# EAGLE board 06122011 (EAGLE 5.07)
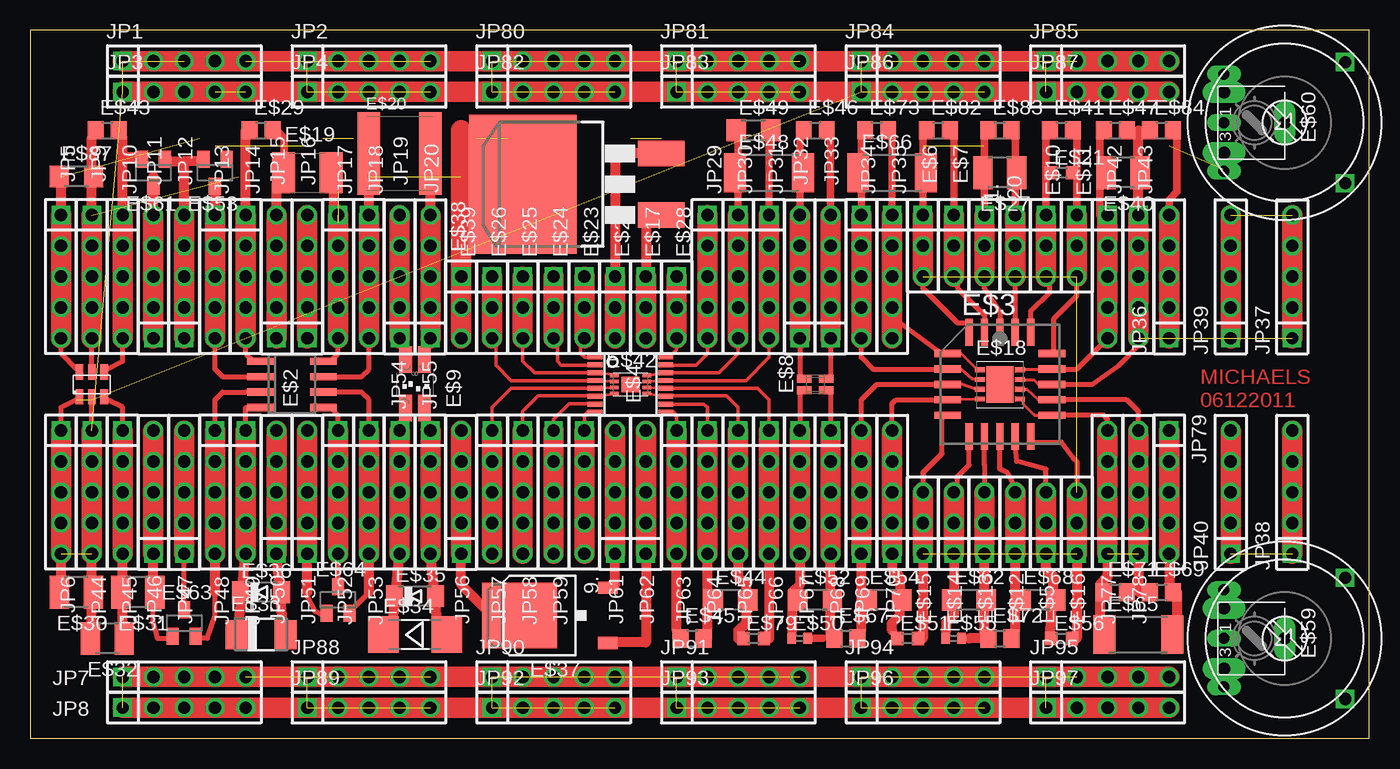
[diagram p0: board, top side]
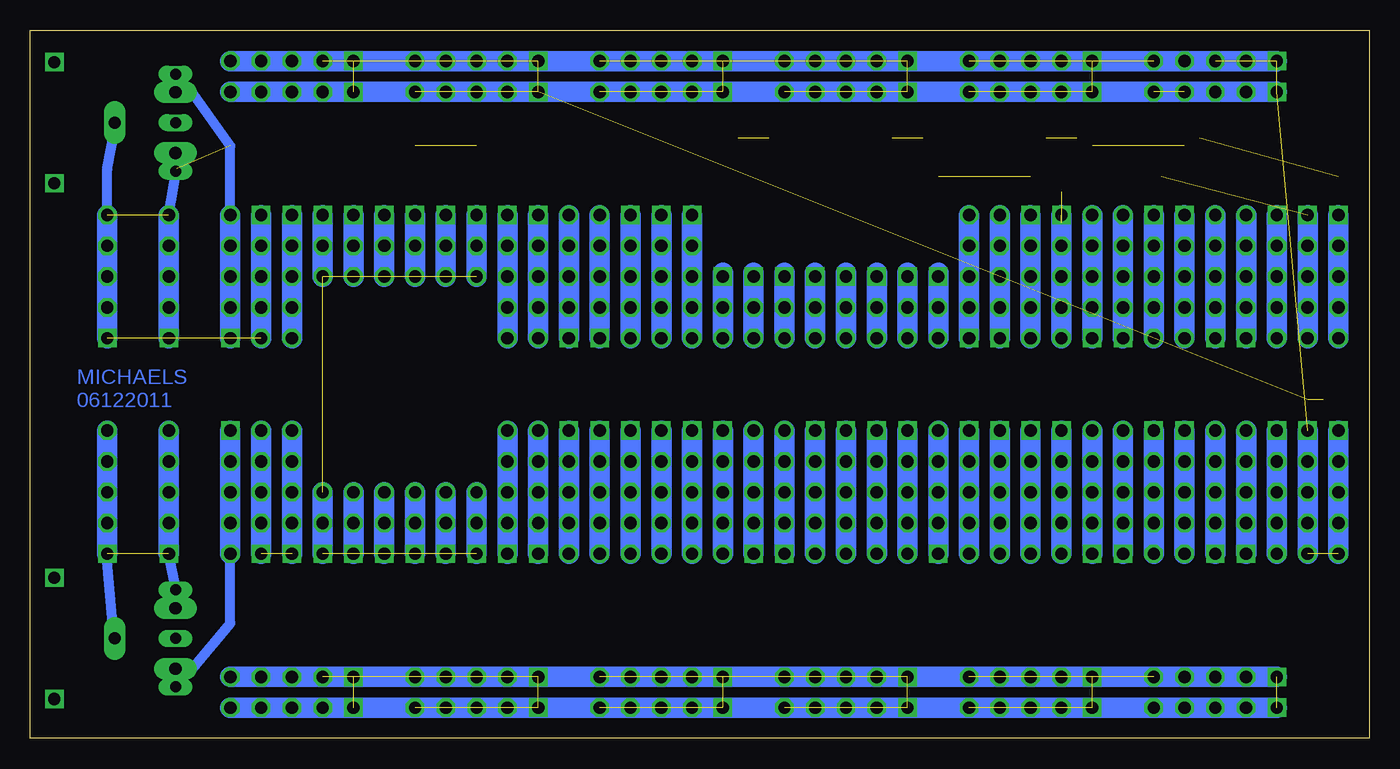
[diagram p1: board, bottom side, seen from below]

Size 110.49 x 58.42 mm. Coordinates in mm from the lower left corner, seen from the top.
Outline: 0,0 110.49,0 110.49,58.42 0,58.42 0,0
Copper layers (1*16): Top 0.035mm / dielectric 1.5mm / Bottom 0.035mm
Design rules "default": minimum track width 10mil, minimum drill 24mil, track to track 8mil, track to pad 8mil, pad to pad 8mil, via to via 8mil, smd to smd 8mil, copper to edge 40mil, drill to drill 8mil, minimum pad ring 10mil, minimum via ring 8mil, stop-mask expansion 4mil, vias tented up to drill 0mil, thermal gap 10mil

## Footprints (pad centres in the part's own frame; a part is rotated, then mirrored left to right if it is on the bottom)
1X03 = drill 1.016 square: 1 -2.54,0 | drill 1.016 octagon: 2 0,0; 3 2.54,0
1X05 = drill 1.016 square: 1 -5.08,0 | drill 1.016 octagon: 2 -2.54,0; 3 0,0; 4 2.54,0; 5 5.08,0
SOT23-6 = smd 0.635 x 1.27: 1 -1.016,-1.016; 2 0,-1.016; 3 1.016,-1.016; 4 1.016,1.016; 5 0,1.016; 6 -1.016,1.016
SO08 = smd 0.6 x 2.2: 1 -1.905,-2.6; 2 -0.635,-2.6; 3 0.635,-2.6; 4 1.905,-2.6; 5 1.905,2.6; 6 0.635,2.6; 7 -0.635,2.6; 8 -1.905,2.6
PLCC20S = smd 0.6 x 2.2: 1 0,4.3; 2 -1.27,4.3; 3 -2.54,4.3; 9 -2.54,-4.3; 10 -1.27,-4.3; 11 0,-4.3; 12 1.27,-4.3; 13 2.54,-4.3; 19 2.54,4.3; 20 1.27,4.3 | smd 2.2 x 0.6: 4 -4.3,2.54; 5 -4.3,1.27; 6 -4.3,0; 7 -4.3,-1.27; 8 -4.3,-2.54; 14 4.3,-2.54; 15 4.3,-1.27; 16 4.3,0; 17 4.3,1.27; 18 4.3,2.54
SSOP16 = smd 0.4 x 1.2: 1 -2.275,-2.925; 2 -1.625,-2.925; 3 -0.975,-2.925; 4 -0.325,-2.925; 5 0.325,-2.925; 6 0.975,-2.925; 7 1.625,-2.925; 8 2.275,-2.925; 9 2.275,2.925; 10 1.625,2.925; 11 0.975,2.925; 12 0.325,2.925; 13 -0.325,2.925; 14 -0.975,2.925; 15 -1.625,2.925; 16 -2.275,2.925
GM1WA55311A = smd 0.65 x 1.2: 1 -0.475,0.9; 2 -0.475,-0.9; 3 0.475,-0.9; 4 0.475,0.9
DUOLEDSMD = smd 1.067 x 2.184: AGRN 0.77,1.95; ARED -0.77,1.95; CGRN 0.77,-2.05; CRED -0.77,-2.05
DFN8-4X4 = smd 0.8 x 0.4: 1 -1.65,1.2; 2 -1.65,0.4; 3 -1.65,-0.4; 4 -1.65,-1.2; 5 1.65,-1.2; 6 1.65,-0.4; 7 1.65,0.4; 8 1.65,1.2 | smd 2.2 x 3: EXP 0,0
C1812 = smd 1.9 x 3.4: 1 -1.95,0; 2 1.95,0
C2225K = smd 1.85 x 6.8: 1 -2.55,0; 2 2.55,0
R0603 = smd 1 x 1.1: 1 -0.85,0; 2 0.85,0
R1210 = smd 1.6 x 2.7: 1 -1.4,0; 2 1.4,0
R0805 = smd 1.3 x 1.5: 1 -0.95,0; 2 0.95,0
DO-214AC = smd 1.8 x 2.4: A 2.025,0; C -2.025,0
MELF-MLL41 = smd 2.5 x 3: A 2.625,0; C -2.625,0
MINIMELF = smd 1.4 x 1.8: A 1.7,0; C -1.7,0
D-PAK_TO252AA = smd 1 x 1.6: 1 -2.28,-4.8; 3 2.28,-4.8 | smd 5.4 x 6.2: 4 0,2.5
D2PACK = smd 2.083 x 3.81: 1 -2.54,-8.89; 3 2.54,-8.89 | smd 11.43 x 8.89: 2 0,2.54
DFN-2X3 = smd 0.7 x 0.3: 1 -1.325,0.75; 2 -1.325,0.25; 3 -1.325,-0.25; 4 -1.325,-0.75; 5 1.325,-0.75; 6 1.325,-0.25; 7 1.325,0.25; 8 1.325,0.75 | smd 1.5 x 1.3: EXP 0,0
R1206 = smd 1.6 x 1.803: 1 -1.422,0; 2 1.422,0
R2512 = smd 1.8 x 3.2: 1 -2.8,0; 2 2.8,0
R0402 = smd 0.7 x 0.9: 1 -0.65,0; 2 0.65,0
SOT23 = smd 1 x 1.4: 1 -0.95,-1.1; 2 0.95,-1.1; 3 0,1.1
RANDL = drill 0.9 long: A -4,5; E 4,5; S 0,5 | drill 1 square: P$1 -5,-5; P$2 5,-5
EVND8AA = drill 1 pad 1.778 long: A -2.5,-2.5; E 2.5,-2.5; S 0,2.5

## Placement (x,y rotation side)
1.  [1X03]  78.74,40.64 270 top
9.  [1X05]  45.72,20.32 270 top
20  [1X03]  81.28,40.64 270 top
E$1  [SOT23-6]  5.08,29.21 0 top
E$2  [SO08]  21.59,29.21 270 top
E$3  [PLCC20S]  80.01,29.21 0 top
E$4  [SSOP16]  49.53,29.21 270 top
E$5  [1X03]  83.82,17.78 90 top
E$6  [1X03]  73.66,40.64 270 top
E$7  [1X03]  76.2,40.64 270 top
E$8  [GM1WA55311A]  64.77,29.21 90 top
E$9  [DUOLEDSMD]  31.75,29.21 180 top
E$10  [1X03]  83.82,40.64 270 top
E$11  [1X03]  86.36,40.64 270 top
E$12  [1X03]  81.28,17.78 90 top
E$13  [1X03]  78.74,17.78 90 top
E$14  [1X03]  76.2,17.78 90 top
E$15  [1X03]  73.66,17.78 90 top
E$16  [1X03]  86.36,17.78 90 top
E$17  [1X03]  50.8,35.56 270 top
E$18  [DFN8-4X4]  80.01,29.21 0 top
E$19  [C1812]  22.86,46.67 0 top
E$20  [C2225K]  30.48,48.26 0 top
E$21  [R0603]  85.09,46.67 0 top
E$22  [1X03]  48.26,35.56 270 top
E$23  [1X03]  45.72,35.56 270 top
E$24  [1X03]  43.18,35.56 270 top
E$25  [1X03]  40.64,35.56 270 top
E$26  [1X03]  38.1,35.56 270 top
E$27  [R1210]  80.01,46.67 180 top
E$28  [1X03]  53.34,35.56 270 top
E$29  [R0805]  19.05,50.16 0 top
E$30  [R1210]  3.81,12.06 180 top
E$31  [R1210]  8.89,12.06 180 top
E$32  [R1210]  6.35,8.26 180 top
E$33  [DO-214AC]  19.05,8.57 0 top
E$34  [MELF-MLL41]  31.75,8.57 0 top
E$35  [MINIMELF]  31.75,11.75 0 top
E$36  [MINIMELF]  19.05,12.06 0 top
E$37  [D-PAK_TO252AA]  42.86,10.16 90 top
E$38  [D2PACK]  43.18,45.72 90 top
E$39  [1X03]  35.56,35.56 270 top
E$40  [R1210]  90.17,46.67 180 top
E$41  [R0805]  85.09,50.16 0 top
E$42  [DFN-2X3]  49.53,29.21 0 top
E$43  [R0805]  6.35,50.16 0 top
E$44  [R1206]  57.78,11.43 0 top
E$45  [R0805]  54.61,8.26 0 top
E$46  [R0805]  64.77,50.16 0 top
E$47  [R0805]  89.53,50.16 0 top
E$48  [R2512]  60.96,46.67 0 top
E$49  [R1206]  59.69,50.16 0 top
E$50  [R0402]  63.5,8.26 0 top
E$51  [R0603]  72.39,8.26 0 top
E$52  [R1206]  64.77,11.43 0 top
E$53  [SOT23]  15.24,46.67 180 top
E$54  [R1206]  70.48,11.43 0 top
E$55  [R0402]  76.2,8.26 0 top
E$56  [R0603]  85.09,8.26 0 top
E$57  [RANDL]  103.5,50.8 90 top
E$58  [RANDL]  103.5,8.26 90 top
E$59  [EVND8AA]  101.02,8.26 270 top
E$60  [EVND8AA]  101.02,50.8 270 top
E$61  [SOT23]  10.16,46.67 180 top
E$62  [R1206]  77.47,11.43 0 top
E$63  [SOT23]  12.7,9.53 0 top
E$64  [SOT23]  25.4,11.43 0 top
E$65  [R2512]  91.44,8.57 0 top
E$66  [R2512]  71.12,46.67 0 top
E$67  [R0805]  67.31,8.26 0 top
E$68  [R1206]  83.19,11.43 0 top
E$69  [R0805]  93.34,12.06 0 top
E$71  [R0805]  89.53,12.06 0 top
E$72  [R0805]  80.01,8.26 0 top
E$73  [R0805]  69.85,50.16 0 top
E$79  [R0603]  59.69,8.26 0 top
E$82  [R0805]  74.93,50.16 0 top
E$83  [R0805]  80.01,50.16 0 top
E$84  [R0805]  93.34,50.16 0 top
E$87  [R1206]  3.81,46.35 0 top
JP1  [1X05]  12.7,55.88 0 top
JP2  [1X05]  27.94,55.88 0 top
JP3  [1X05]  12.7,53.34 0 top
JP4  [1X05]  27.94,53.34 0 top
JP5  [1X05]  2.54,38.1 270 top
JP6  [1X05]  2.54,20.32 270 top
JP7  [1X05]  12.7,5.08 0 top
JP8  [1X05]  12.7,2.54 0 top
JP9  [1X05]  5.08,38.1 270 top
JP10  [1X05]  7.62,38.1 270 top
JP11  [1X05]  10.16,38.1 90 top
JP12  [1X05]  12.7,38.1 90 top
JP13  [1X05]  15.24,38.1 270 top
JP14  [1X05]  17.78,38.1 270 top
JP15  [1X05]  20.32,38.1 90 top
JP16  [1X05]  22.86,38.1 90 top
JP17  [1X05]  25.4,38.1 270 top
JP18  [1X05]  27.94,38.1 270 top
JP19  [1X05]  30.48,38.1 90 top
JP20  [1X05]  33.02,38.1 90 top
JP29  [1X05]  55.88,38.1 270 top
JP30  [1X05]  58.42,38.1 270 top
JP31  [1X05]  60.96,38.1 270 top
JP32  [1X05]  63.5,38.1 90 top
JP33  [1X05]  66.04,38.1 90 top
JP34  [1X05]  68.58,38.1 270 top
JP35  [1X05]  71.12,38.1 270 top
JP36  [1X05]  93.98,38.1 90 top
JP37  [1X05]  104.14,38.1 90 top
JP38  [1X05]  104.14,20.32 90 top
JP39  [1X05]  99.06,38.1 90 top
JP40  [1X05]  99.06,20.32 90 top
JP42  [1X05]  88.9,38.1 270 top
JP43  [1X05]  91.44,38.1 270 top
JP44  [1X05]  5.08,20.32 270 top
JP45  [1X05]  7.62,20.32 270 top
JP46  [1X05]  10.16,20.32 90 top
JP47  [1X05]  12.7,20.32 90 top
JP48  [1X05]  15.24,20.32 270 top
JP49  [1X05]  17.78,20.32 270 top
JP50  [1X05]  20.32,20.32 90 top
JP51  [1X05]  22.86,20.32 90 top
JP52  [1X05]  25.4,20.32 270 top
JP53  [1X05]  27.94,20.32 270 top
JP54  [1X05]  30.48,20.32 270 top
JP55  [1X05]  33.02,20.32 270 top
JP56  [1X05]  35.56,20.32 90 top
JP57  [1X05]  38.1,20.32 270 top
JP58  [1X05]  40.64,20.32 270 top
JP59  [1X05]  43.18,20.32 270 top
JP61  [1X05]  48.26,20.32 90 top
JP62  [1X05]  50.8,20.32 90 top
JP63  [1X05]  53.34,20.32 270 top
JP64  [1X05]  55.88,20.32 270 top
JP65  [1X05]  58.42,20.32 270 top
JP66  [1X05]  60.96,20.32 270 top
JP67  [1X05]  63.5,20.32 270 top
JP68  [1X05]  66.04,20.32 270 top
JP69  [1X05]  68.58,20.32 90 top
JP70  [1X05]  71.12,20.32 90 top
JP77  [1X05]  88.9,20.32 90 top
JP78  [1X05]  91.44,20.32 90 top
JP79  [1X05]  93.98,20.32 270 top
JP80  [1X05]  43.18,55.88 0 top
JP81  [1X05]  58.42,55.88 0 top
JP82  [1X05]  43.18,53.34 0 top
JP83  [1X05]  58.42,53.34 0 top
JP84  [1X05]  73.66,55.88 0 top
JP85  [1X05]  88.9,55.88 0 top
JP86  [1X05]  73.66,53.34 0 top
JP87  [1X05]  88.9,53.34 0 top
JP88  [1X05]  27.94,5.08 0 top
JP89  [1X05]  27.94,2.54 0 top
JP90  [1X05]  43.18,5.08 0 top
JP91  [1X05]  58.42,5.08 0 top
JP92  [1X05]  43.18,2.54 0 top
JP93  [1X05]  58.42,2.54 0 top
JP94  [1X05]  73.66,5.08 0 top
JP95  [1X05]  88.9,5.08 0 top
JP96  [1X05]  73.66,2.54 0 top
JP97  [1X05]  88.9,2.54 0 top

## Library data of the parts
1. 9. 20 E$5-E$7 E$10-E$17 E$22-E$26 E$28 E$39 JP1-JP20 JP29-JP40 JP42-JP59 JP61-JP70 JP77-JP97 = pinhead(2)
E$1 = microchip-5
E$2-E$4 = linear
E$8 E$9 = led
E$18 E$42 = microchip
E$19-E$21 E$27 E$29-E$32 E$40 E$41 E$43-E$52 E$54-E$56 E$62 E$65-E$69 E$71-E$73 E$79 E$82-E$84 E$87 = rcl
E$33-E$36 = diode
E$37 E$38 = transistor-power
E$53 E$61 E$63 E$64 = transistor-npn
E$57-E$60 = pot

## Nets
N$1: JP1.1 JP1.2 JP1.3
N$2: JP2.1 JP2.2
N$3: JP3.4 JP3.5
N$76: JP80.1 JP80.2 JP80.3
N$77: JP81.1 JP81.2
N$78: JP82.4 JP82.5
N$80: JP84.1 JP84.2 JP84.3
N$81: JP85.1 JP85.2
N$82: JP86.4 JP86.5
N$84: JP88.1 JP88.2
N$86: JP90.1 JP90.2 JP90.3
N$87: JP91.1 JP91.2
N$88: JP92.4 JP92.5
N$90: JP94.1 JP94.2 JP94.3
N$91: JP95.1 JP95.2
N$92: JP96.4 JP96.5
S$25: 20.3
S$30: E$7.3
S$31: E$6.3
S$42: E$5.1
S$43: E$14.3
S$45: E$17.1

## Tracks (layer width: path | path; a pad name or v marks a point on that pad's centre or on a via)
N$1  (2 unrouted)
N$2  (1 unrouted)
N$3  (1 unrouted)
N$4  (1 unrouted)
  Top 0.406: 3.81,30.48 2.54,31.75 2.54,33.02
  Top 0.813: 2.54,43.18 2.54,46.35
  Top 1.676: 2.54,33.02 2.54,43.18
N$5  (1 unrouted)
  Top 0.406: 5.08,30.48 5.08,33.02
  Top 0.813: 5.08,43.18 5.08,49.53
  Top 1.676: 5.08,33.02 5.08,43.18
N$6
  Top 0.406: 6.35,30.48 7.62,31.11 7.62,33.02
  Top 0.813: 7.62,43.18 7.62,49.53
  Top 1.676: 7.62,33.02 7.62,43.18
N$7  (3 unrouted)
  Top 0.406: 85.09,29.21 87.63,29.21 89.85,30.8 91.44,32.38 91.44,33.02
  Top 0.61: 93.98,43.18 93.98,44.45 94.61,45.09 94.61,50.16
  Top 1.676: 91.44,33.02 91.44,43.18 | 93.98,33.02 93.98,43.18 | 99.06,33.02 99.06,43.18 | 104.14,33.02 104.14,43.18
N$8
  Top 1.676: 88.9,33.02 88.9,43.18
N$10
  Top 0.813: 68.58,8.89 68.58,15.24
N$11
  Top 0.813: 66.04,12.06 66.04,15.24
N$12
  Top 0.406: 66.04,11.43 66.04,12.06
  Top 0.813: 66.04,8.26 66.04,11.43
N$14
  Top 0.813: 81.28,8.89 81.28,15.24
N$15
  Top 0.305: 71.44,37.15 71.12,37.47 71.12,38.1
  Top 0.406: 75.25,31.75 71.75,34.29 71.44,37.15
  Top 0.61: 71.12,43.18 71.12,50.16
  Top 1.676: 71.12,33.02 71.12,38.1 71.12,43.18
N$16
  Top 0.813: 78.74,12.06 78.74,15.24
N$17
  Top 0.406: 78.74,11.43 78.74,12.06
  Top 0.813: 78.74,8.26 78.74,11.43
N$18
  Top 0.406: 11.75,8.26 10.48,8.26 10.16,9.53 10.16,12.7
  Top 0.813: 10.16,12.06 10.16,12.7 10.16,15.24
N$19
  Top 0.61: 60.96,43.18 60.96,49.53
  Top 1.676: 60.96,33.02 60.96,43.18
N$20
  Top 0.305: 52.7,30.16 56.83,30.16 58.42,31.75 58.42,33.02
  Top 0.61: 58.42,43.18 58.42,49.85
  Top 1.676: 58.42,33.02 58.42,43.18
N$21
  Top 0.305: 52.7,30.8 54.93,30.8 55.88,31.75 55.88,33.02
  Top 1.676: 55.88,33.02 55.88,43.18
N$25
  Top 0.305: 46.04,31.43 45.72,31.43 45.4,31.75 45.4,32.7 45.72,33.02
N$26
  Top 0.305: 46.04,30.8 43.81,30.8 43.5,31.11 43.5,32.7 43.18,33.02
N$27
  Top 0.305: 46.04,30.16 41.59,30.16 40.64,31.11 40.64,33.02
N$28
  Top 0.305: 46.35,29.53 39.69,29.53 38.42,30.8 38.42,32.7 38.1,33.02
N$29
  Top 1.676: 35.56,33.02 35.56,50.16
N$30
  Top 0.813: 33.02,43.18 33.02,45.72
  Top 1.676: 33.02,33.02 33.02,43.18
N$31
  Top 1.676: 30.48,33.02 30.48,43.18
N$32
  Top 0.406: 24.77,29.84 27.3,29.84 27.94,30.48 27.94,33.02
  Top 0.813: 27.94,43.18 27.94,46.04
  Top 1.676: 27.94,33.02 27.94,43.18
N$33  (2 unrouted)
  Top 0.406: 24.77,31.11 25.4,31.75 25.4,33.02
  Top 1.676: 25.4,33.02 25.4,43.18
N$34
  Top 1.676: 22.86,33.02 22.86,43.18
N$35
  Top 1.676: 20.32,33.02 20.32,43.18
N$36
  Top 0.406: 18.41,31.11 17.78,31.75 17.78,33.02
  Top 1.676: 17.78,33.02 17.78,43.18
N$37
  Top 0.406: 18.41,29.84 15.88,29.84 15.24,30.48 15.24,33.02
  Top 1.676: 15.24,33.02 15.24,43.18
N$38
  Top 1.676: 12.7,33.02 12.7,43.18
N$39
  Top 0.813: 10.16,43.18 10.16,46.35
  Top 1.676: 10.16,33.02 10.16,43.18
N$40  (5 unrouted)
  Top 0.406: 3.81,27.94 2.54,27.3 2.54,25.4 | 5.08,25.4 5.08,27.94
  Top 1.676: 5.08,15.24 5.08,25.4 | 83.82,55.88 93.98,55.88 | 83.82,53.34 93.98,53.34 | 68.58,53.34 78.74,53.34 | 68.58,55.88 78.74,55.88 | 2.54,15.24 2.54,25.4
N$41
  Top 0.813: 93.98,15.24 93.98,12.7 94.61,12.06 94.61,8.26
  Top 1.676: 93.98,15.24 93.98,25.4
N$42
  Top 0.406: 85.41,27.94 90.49,27.94 91.44,26.99 91.44,25.08
  Top 0.813: 91.44,15.24 91.44,12.06
  Top 1.676: 91.44,15.24 91.44,25.08 91.44,25.4
N$43
  Top 0.406: 85.41,26.67 88.58,26.67 88.9,26.35 88.9,25.4
  Top 1.676: 88.9,15.24 88.9,25.4
N$44
  Top 0.813: 7.62,8.89 7.62,15.24
N$45
  Top 0.406: 82.55,24.45 85.09,24.45 86.04,23.18 86.36,22.86 86.36,20.64
N$46
  Top 0.813: 5.08,8.89 5.08,15.24
N$47
  Top 0.406: 80.01,23.81 80.01,22.23 80.64,21.91 81.28,20.64
N$48
  Top 0.406: 78.74,24.13 78.74,22.54 78.74,20.64
N$49
  Top 0.813: 2.54,12.06 2.54,15.24
N$50
  Top 0.305: 71.12,25.4 71.12,25.72
  Top 0.406: 74.93,27.94 71.44,27.94 71.12,27.62 71.12,25.72
  Top 1.676: 71.12,15.24 71.12,25.4
N$51
  Top 0.406: 74.93,29.21 69.85,29.21 68.58,27.94 68.58,25.4
  Top 1.676: 68.58,15.24 68.58,25.4
N$52
  Top 1.676: 66.04,15.24 66.04,25.4
N$53
  Top 0.813: 63.5,15.24 63.5,12.7 62.87,12.06 62.87,8.89
  Top 1.676: 63.5,15.24 63.5,25.4
N$54
  Top 0.813: 60.96,15.24 60.96,8.26
  Top 1.676: 60.96,15.24 60.96,25.4
N$55
  Top 0.305: 52.39,28.26 57.47,28.26 58.42,27.3 58.42,25.4
  Top 1.676: 58.42,15.24 58.42,25.4
N$56
  Top 0.305: 52.7,27.56 55.56,27.56 55.88,27.3 55.88,25.4
  Top 1.676: 55.88,15.24 55.88,25.4
N$57
  Top 0.305: 53.02,26.99 53.34,26.67 53.34,25.08
  Top 1.676: 53.34,15.24 53.34,25.08 53.34,25.4
N$58
  Top 0.813: 50.8,15.24 50.8,7.94 48.26,7.94
  Top 1.676: 50.8,15.24 50.8,25.4
N$59
  Top 0.813: 48.26,12.7 48.26,15.24
  Top 1.676: 48.26,15.24 48.26,25.4
N$60
  Top 0.305: 46.35,26.99 46.04,26.99 45.72,26.67 45.72,25.4
  Top 1.676: 45.72,15.24 45.72,25.4
N$61
  Top 0.305: 46.04,27.62 44.45,27.62 43.18,26.35 43.18,25.4
  Top 1.676: 43.18,15.24 43.18,25.4
N$62
  Top 0.305: 46.04,28.26 41.91,28.26 40.64,26.99 40.64,25.4
  Top 1.676: 40.64,15.24 40.64,25.4
N$63
  Top 0.305: 46.04,28.89 39.69,28.89 38.1,27.3 38.1,25.4
  Top 1.676: 38.1,15.24 38.1,25.4
N$64
  Top 1.676: 35.56,15.24 35.56,25.4
N$65
  Top 1.676: 33.02,15.24 33.02,25.4
N$66
  Top 1.676: 30.48,15.24 30.48,25.4
N$67
  Top 0.406: 24.77,28.57 27.3,28.57 27.94,27.94 27.94,25.4
  Top 1.676: 27.94,15.24 27.94,25.4
N$68
  Top 0.406: 24.77,27.3 25.4,26.67 25.4,25.4
  Top 1.676: 25.4,15.24 25.4,25.4
N$69
  Top 1.676: 22.86,15.24 22.86,25.4
N$70
  Top 1.676: 20.32,15.24 20.32,25.4
N$71
  Top 0.406: 17.78,25.4 17.78,27.3
  Top 1.676: 17.78,15.24 17.78,25.4
N$72
  Top 0.406: 17.78,28.57 15.88,28.57 15.24,27.94 15.24,25.4
  Top 1.676: 15.24,15.24 15.24,25.4
N$73
  Top 0.406: 12.7,10.16 12.7,15.24
  Top 1.676: 12.7,15.24 12.7,25.4
N$74
  Top 1.676: 10.16,15.24 10.16,25.4
N$75
  Top 0.406: 6.35,27.94 7.62,27.3 7.62,25.4
  Top 1.676: 7.62,15.24 7.62,25.4
N$76  (2 unrouted)
N$77  (1 unrouted)
N$78  (1 unrouted)
N$79  (3 unrouted)
  Top 1.676: 53.34,55.88 63.5,55.88 | 53.34,53.34 63.5,53.34 | 38.1,53.34 48.26,53.34 | 38.1,55.88 48.26,55.88
N$80  (2 unrouted)
N$81  (1 unrouted)
N$82  (1 unrouted)
N$83  (3 unrouted)
  Top 1.676: 22.86,55.88 33.02,55.88 | 22.86,53.34 33.02,53.34 | 7.62,53.34 17.78,53.34 | 7.62,55.88 17.78,55.88
N$84  (1 unrouted)
N$85  (3 unrouted)
  Top 1.676: 68.58,2.54 78.74,2.54 | 68.58,5.08 78.74,5.08 | 83.82,5.08 93.98,5.08 | 83.82,2.54 93.98,2.54
N$86  (2 unrouted)
N$87  (1 unrouted)
N$88  (1 unrouted)
N$89  (3 unrouted)
  Top 1.676: 53.34,5.08 63.5,5.08 | 53.34,2.54 63.5,2.54 | 38.1,2.54 48.26,2.54 | 38.1,5.08 48.26,5.08
N$90  (2 unrouted)
N$91  (1 unrouted)
N$92  (1 unrouted)
N$93  (3 unrouted)
  Top 1.676: 22.86,5.08 33.02,5.08 | 22.86,2.54 33.02,2.54 | 7.62,2.54 17.78,2.54 | 7.62,5.08 17.78,5.08
N$94
  Bottom 1.676: 2.54,33.02 2.54,43.18
N$95
  Bottom 1.676: 5.08,33.02 5.08,43.18
N$96
  Bottom 1.676: 7.62,33.02 7.62,43.18
N$97
  Bottom 1.676: 10.16,33.02 10.16,43.18
N$98
  Bottom 1.676: 12.7,33.02 12.7,43.18
N$99
  Bottom 1.676: 15.24,33.02 15.24,43.18
N$100
  Bottom 1.676: 17.78,33.02 17.78,43.18
N$101
  Bottom 1.676: 20.32,33.02 20.32,43.18
N$102
  Bottom 1.676: 22.86,33.02 22.86,43.18
N$103
  Bottom 1.676: 25.4,33.02 25.4,43.18
N$104
  Bottom 1.676: 27.94,33.02 27.94,43.18
N$105
  Bottom 1.676: 30.48,33.02 30.48,43.18
N$106
  Bottom 1.676: 33.02,33.02 33.02,43.18
N$107
  Bottom 1.676: 35.56,33.02 35.56,38.42
N$108
  Bottom 1.676: 38.1,33.02 38.1,38.42
N$109
  Bottom 1.676: 40.64,33.02 40.64,38.42
N$110
  Bottom 1.676: 43.18,33.02 43.18,38.42
N$111
  Bottom 1.676: 45.72,33.02 45.72,38.42
N$112
  Bottom 1.676: 48.26,33.02 48.26,38.42
N$113
  Bottom 1.676: 50.8,33.02 50.8,38.42
N$114
  Bottom 1.676: 53.34,33.02 53.34,38.42
N$115
  Bottom 1.676: 55.88,33.02 55.88,43.18
N$116
  Bottom 1.676: 58.42,33.02 58.42,43.18
N$117
  Bottom 1.676: 60.96,33.02 60.96,43.18
N$118
  Bottom 1.676: 63.5,33.02 63.5,43.18
N$119
  Bottom 1.676: 66.04,33.02 66.04,43.18
N$120
  Bottom 1.676: 68.58,33.02 68.58,43.18
N$121
  Bottom 1.676: 71.12,33.02 71.12,43.18
N$122
  Top 0.813: 22.86,12.06 22.86,15.24
N$123
  Top 0.813: 20.95,8.26 20.32,15.24
N$124
  Top 0.813: 17.14,8.89 17.78,15.24
N$125
  Top 0.406: 13.65,8.26 14.61,8.26 15.24,10.16 15.24,12.06
  Top 0.813: 15.24,12.06 15.24,15.24
N$126
  Top 0.813: 35.56,15.24 35.56,12.7 38.73,9.53
N$127
  Top 0.813: 33.66,8.89 33.02,15.24
N$128
  Bottom 1.676: 88.9,33.02 88.9,43.18
N$129  (3 unrouted)
  Bottom 0.813: 97.16,53.34 93.98,48.9 93.98,42.55 | 103.5,50.16 104.14,46.99 104.14,43.18 | 99.06,43.18 98.42,46.99
  Bottom 1.676: 104.14,33.02 104.14,43.18 | 93.98,43.18 93.98,42.55 93.98,33.02 | 91.44,33.02 91.44,43.18 | 99.06,33.02 99.06,43.18
N$130  (5 unrouted)
  Bottom 1.676: 5.08,15.24 5.08,25.4 | 7.62,55.88 17.78,55.88 | 7.62,53.34 17.78,53.34 | 22.86,53.34 33.02,53.34 | 22.86,55.88 33.02,55.88 | 2.54,15.24 2.54,25.4
N$131
  Bottom 1.676: 7.62,15.24 7.62,25.4
N$132
  Bottom 1.676: 10.16,15.24 10.16,25.4
N$133
  Bottom 1.676: 12.7,15.24 12.7,25.4
N$134
  Bottom 1.676: 15.24,15.24 15.24,25.4
N$135
  Bottom 1.676: 17.78,15.24 17.78,25.4
N$136
  Bottom 1.676: 20.32,15.24 20.32,25.4
N$137
  Bottom 1.676: 22.86,15.24 22.86,25.4
N$138
  Bottom 1.676: 25.4,15.24 25.4,25.4
N$139
  Bottom 1.676: 27.94,15.24 27.94,25.4
N$140
  Bottom 1.676: 30.48,15.24 30.48,25.4
N$141
  Bottom 1.676: 33.02,15.24 33.02,25.4
N$142
  Bottom 1.676: 35.56,15.24 35.56,25.4
N$143
  Bottom 1.676: 38.1,15.24 38.1,25.4
N$144
  Bottom 1.676: 40.64,15.24 40.64,25.4
N$145
  Bottom 1.676: 43.18,15.24 43.18,25.4
N$146
  Bottom 1.676: 45.72,15.24 45.72,25.4
N$147
  Bottom 1.676: 48.26,15.24 48.26,25.4
N$148
  Bottom 1.676: 50.8,15.24 50.8,25.4
N$149
  Bottom 1.676: 53.34,15.24 53.34,25.4
N$150
  Bottom 1.676: 55.88,15.24 55.88,25.4
N$151
  Bottom 1.676: 58.42,15.24 58.42,25.4
N$152
  Bottom 1.676: 60.96,15.24 60.96,25.4
N$153
  Bottom 1.676: 63.5,15.24 63.5,25.4
N$154
  Bottom 1.676: 66.04,15.24 66.04,25.4
N$155
  Bottom 1.676: 68.58,15.24 68.58,25.4
N$156
  Bottom 1.676: 71.12,15.24 71.12,25.4
N$157
  Top 0.813: 29.84,8.89 30.48,15.24
N$158
  Top 0.813: 27.94,12.06 27.94,15.24
N$161  (23 unrouted)
  Top 0.61: 73.66,43.18 73.66,50.16 | 76.2,43.18 76.2,50.16 | 78.74,43.18 78.74,50.16 | 81.28,43.18 81.28,50.16 | 83.82,43.18 83.82,50.16 | 86.36,43.18 86.36,50.16
  Top 0.813: 73.66,15.24 73.66,8.26
  Top 1.676: 73.66,38.1 73.66,43.18 | 76.2,38.1 76.2,43.18 | 78.74,38.1 78.74,43.18 | 81.28,38.1 81.28,43.18 | 83.82,38.1 83.82,43.18 | 86.36,38.1 86.36,43.18 | 86.36,15.24 86.36,20.32 | 83.82,15.24 83.82,20.32 | 81.28,15.24 81.28,20.32 | 78.74,15.24 78.74,20.32 | 76.2,15.24 76.2,20.32 | 73.66,15.24 73.66,20.32 | 50.8,33.02 50.8,38.1 | 53.34,33.02 53.34,38.1 | 48.26,33.02 48.26,38.1 | 45.72,33.02 45.72,38.1 | 43.18,33.02 43.18,38.1 | 40.64,33.02 40.64,38.1 | 38.1,33.02 38.1,38.1
  Bottom 1.676: 83.82,15.24 83.82,20.32 | 81.28,15.24 81.28,20.32 | 78.74,15.24 78.74,20.32 | 76.2,15.24 76.2,20.32 | 73.66,15.24 73.66,20.32 | 86.36,15.24 86.36,20.32 | 86.36,38.1 86.36,43.18 | 83.82,38.1 83.82,43.18 | 81.28,38.1 81.28,43.18 | 78.74,38.1 78.74,43.18 | 76.2,38.1 76.2,43.18 | 73.66,38.1 73.66,43.18
N$164  (1 unrouted)
  Bottom 1.676: 91.44,15.24 91.44,25.4 | 88.9,15.24 88.9,25.4
N$165
  Bottom 0.813: 97.16,5.71 93.98,9.53 93.98,15.24
  Bottom 1.676: 93.98,15.24 93.98,25.4
N$166  (3 unrouted)
  Bottom 1.676: 38.1,55.88 48.26,55.88 | 38.1,53.34 48.26,53.34 | 53.34,53.34 63.5,53.34 | 53.34,55.88 63.5,55.88
N$167  (3 unrouted)
  Bottom 1.676: 68.58,55.88 78.74,55.88 | 68.58,53.34 78.74,53.34 | 83.82,53.34 93.98,53.34 | 83.82,55.88 93.98,55.88
N$168  (3 unrouted)
  Bottom 1.676: 22.86,2.54 33.02,2.54 | 22.86,5.08 33.02,5.08 | 7.62,5.08 17.78,5.08 | 7.62,2.54 17.78,2.54
N$169  (3 unrouted)
  Bottom 1.676: 38.1,5.08 48.26,5.08 | 38.1,2.54 48.26,2.54 | 53.34,2.54 63.5,2.54 | 53.34,5.08 63.5,5.08
N$170  (3 unrouted)
  Bottom 1.676: 68.58,5.08 78.74,5.08 | 68.58,2.54 78.74,2.54 | 83.82,2.54 93.98,2.54 | 83.82,5.08 93.98,5.08
N$173
  Top 0.813: 55.88,15.24 55.88,13.97 55.88,8.89 55.88,8.26
N$174
  Top 0.813: 53.34,8.89 53.34,15.24
N$191  (1 unrouted)
  Top 1.676: 99.06,15.24 99.06,25.4 | 104.14,15.24 104.14,25.4
N$192
  Bottom 0.813: 103.5,7.62 104.14,14.61 104.14,15.24
  Bottom 1.676: 104.14,15.24 104.14,25.4
N$193  (1 unrouted)
  Top 0.406: 39.37,49.53 40.01,49.53 40.64,48.9 40.64,46.35
N$194
  Top 0.406: 38.1,43.18 38.1,46.99
N$195  (1 unrouted)
N$199  (1 unrouted)
N$201
  Top 0.406: 25.4,13.34 25.4,15.24
N$202
  Top 0.406: 24.13,10.16 23.5,10.48 22.86,11.75 22.86,12.7
N$203
  Top 0.406: 26.67,10.79 27.94,12.06
S$1
  Top 1.676: 78.74,55.88 83.82,55.88
S$2
  Top 1.676: 78.74,53.34 83.82,53.34
S$3  (1 unrouted)
  Top 1.676: 48.26,55.88 53.34,55.88 | 63.5,55.88 68.58,55.88
S$4  (1 unrouted)
  Top 1.676: 48.26,53.34 53.34,53.34 | 63.5,53.34 68.58,53.34
S$5  (1 unrouted)
  Top 1.676: 17.78,55.88 22.86,55.88 | 33.02,55.88 38.1,55.88
S$6  (1 unrouted)
  Top 1.676: 17.78,53.34 22.86,53.34 | 33.02,53.34 38.1,53.34
S$7
  Top 1.676: 78.74,5.08 83.82,5.08
S$8
  Top 1.676: 78.74,2.54 83.82,2.54
S$9  (1 unrouted)
  Top 1.676: 48.26,5.08 53.34,5.08 | 63.5,5.08 68.58,5.08
S$10  (1 unrouted)
  Top 1.676: 48.26,2.54 53.34,2.54 | 63.5,2.54 68.58,2.54
S$11  (1 unrouted)
  Top 1.676: 17.78,5.08 22.86,5.08 | 33.02,5.08 38.1,5.08
S$12  (1 unrouted)
  Top 1.676: 17.78,2.54 22.86,2.54 | 33.02,2.54 38.1,2.54
S$13
  Bottom 1.676: 17.78,55.88 22.86,55.88
S$14
  Bottom 1.676: 17.78,53.34 22.86,53.34
S$15  (1 unrouted)
  Bottom 1.676: 48.26,55.88 53.34,55.88 | 33.02,55.88 38.1,55.88
S$16  (1 unrouted)
  Bottom 1.676: 48.26,53.34 53.34,53.34 | 33.02,53.34 38.1,53.34
S$17  (1 unrouted)
  Bottom 1.676: 78.74,55.88 83.82,55.88 | 63.5,55.88 68.58,55.88
S$18  (1 unrouted)
  Bottom 1.676: 78.74,53.34 83.82,53.34 | 63.5,53.34 68.58,53.34
S$19
  Bottom 1.676: 17.78,5.08 22.86,5.08
S$20
  Bottom 1.676: 17.78,2.54 22.86,2.54
S$21  (1 unrouted)
  Bottom 1.676: 48.26,5.08 53.34,5.08 | 33.02,5.08 38.1,5.08
S$22  (1 unrouted)
  Bottom 1.676: 48.26,2.54 53.34,2.54 | 33.02,2.54 38.1,2.54
S$23  (1 unrouted)
  Bottom 1.676: 78.74,5.08 83.82,5.08 | 63.5,5.08 68.58,5.08
S$24  (1 unrouted)
  Bottom 1.676: 78.74,2.54 83.82,2.54 | 63.5,2.54 68.58,2.54
S$25
  Top 0.406: 81.28,34.61 20.3
S$26
  Top 0.406: 66.04,33.02 66.04,29.84
  Top 1.676: 66.04,33.02 66.04,43.18
S$27
  Top 0.305: 63.5,43.18 63.18,42.86
  Top 0.406: 63.5,33.02 63.5,29.84
  Top 0.61: 63.5,50.16 63.5,43.18
  Top 1.676: 63.5,33.02 63.5,43.18
S$28
  Top 0.406: 80.01,34.29 80.01,35.24 78.74,37.15 78.74,37.78
S$29
  Top 0.305: 52.7,31.43 53.34,32.07 53.34,32.7 53.66,33.02
S$30
  Top 0.406: 78.74,34.29 78.74,34.92 76.52,37.15 76.52,37.78 E$7.3
S$31
  Top 0.406: 77.47,34.29 76.52,34.29 73.66,37.15 E$6.3
S$32
  Top 0.305: 52.7,29.53 59.05,29.53 60.96,31.43 60.96,32.7
S$33
  Top 0.305: 52.7,28.89 60.01,28.89 60.96,27.94 60.96,25.72
S$34
  Top 0.61: 88.27,43.18 88.27,50.16
S$35
  Top 0.406: 82.55,33.97 82.55,35.24 84.14,36.83 84.14,37.47 83.82,37.78
S$36
  Top 0.406: 84.45,32.07 84.45,34.61 86.36,36.51 86.36,37.78
S$37
  Top 0.406: 84.77,30.48 86.36,30.48 88.58,32.7
S$38  (1 unrouted)
S$39
  Top 0.305: 91.12,26.04 91.44,25.72
S$40
  Bottom 0.813: 98.42,12.06 99.06,15.24
  Bottom 1.676: 99.06,15.24 99.06,25.4
S$41  (1 unrouted)
S$42
  Top 0.406: 81.28,24.13 81.41,22.86 83.82,22.23 E$5.1
S$43
  Top 0.406: 77.47,23.81 77.47,22.54 76.52,21.59 76.52,20.64 E$14.3
S$44
  Top 0.406: 75.25,26.35 75.25,23.5 73.66,21.91 73.66,20.64
S$45
  Top 0.813: 52.7,42.55 50.8,42.55 E$17.1
S$46
  Top 0.813: 51.44,48.26 48.26,48.26 48.26,37.47
S$47
  Top 0.61: 64.14,8.26 65.41,8.26
S$48
  Top 0.813: 58.42,14.61 58.42,13.34 59.05,12.7 59.05,9.53 58.42,8.89 58.42,8.26
S$49
  Top 0.813: 71.12,8.89 71.12,9.53 71.75,10.16 71.75,11.43
S$50
  Top 0.813: 71.12,14.61 71.12,13.97 71.75,13.34 71.75,12.06
S$51
  Top 0.813: 76.2,14.61 76.2,10.16 75.56,9.53 75.56,8.89
S$52
  Top 0.813: 83.82,14.61 83.82,13.97 84.45,13.34 84.14,8.26
S$53
  Top 0.813: 86.36,14.61 86.36,8.26
S$54
  Top 0.813: 88.9,14.61 88.9,13.34 88.27,12.7 88.27,10.16
S$55
  Top 0.61: 66.04,43.81 66.04,50.16
S$56
  Top 0.406: 74.61,30.48 69.53,30.48 68.58,31.43 68.58,33.02
  Top 0.61: 68.58,50.16 68.58,43.18
  Top 1.676: 68.58,33.02 68.58,43.18
S$57
  Top 0.813: 25.08,43.5 25.08,45.4 24.77,45.72
S$58
  Top 0.61: 20.95,48.26 20.95,49.53 20.32,50.16
S$59
  Top 0.813: 91.44,43.81 91.44,50.16
S$60
  Top 0.813: 78.74,8.26 77.47,8.26
S$61
  Top 0.406: 63.5,28.57 63.5,26.04
S$62
  Top 0.406: 66.04,28.57 66.04,26.04
S$63
  Top 0.254: 48.26,29.97 46.99,30.16
S$64
  Top 0.254: 46.99,29.53 47.94,29.46
S$65
  Top 0.254: 47.94,28.93 46.99,28.89
S$66
  Top 0.254: 46.99,28.26 48.07,28.45
S$67
  Top 0.254: 51.12,28.45 52.07,28.26
S$68
  Top 0.254: 51.12,28.96 52.39,28.89
S$69
  Top 0.254: 51.12,29.46 52.39,29.53
S$70
  Top 0.254: 51.05,29.97 52.07,30.16
S$71
  Top 0.254: 78.11,30.48 76.83,31.75 76.52,31.75
S$72
  Top 0.254: 78.17,29.59 77.79,29.65 76.83,30.48 76.52,30.48
S$73
  Top 0.254: 78.11,28 76.52,27.94
S$74
  Top 0.254: 78.11,28.77 76.83,29.21 76.52,29.21
S$75
  Top 0.254: 81.92,30.48 83.82,30.48
S$76
  Top 0.254: 81.85,29.59 82.8,29.59 83.19,29.21 84.45,29.21
S$77
  Top 0.254: 81.92,28.83 82.23,28.83 83.19,27.94 83.82,27.94
S$78
  Top 0.254: 81.92,27.94 81.92,27.62 82.87,26.67 84.45,26.67
S$79
  Top 0.813: 20.32,43.5 20.32,45.72 20.95,46.35
S$80
  Top 0.813: 15.24,43.18 15.24,43.5 15.24,43.81 15.24,45.09
S$81  (1 unrouted)
S$82
  Top 0.813: 17.78,43.81 17.78,50.16
S$83
  Top 0.813: 13.97,47.62 13.02,47.62
S$84
  Top 0.813: 12.7,43.5 12.7,47.62 11.43,47.62
S$85
  Top 0.813: 9.21,47.94 7.94,47.94

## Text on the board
Top: MICHAELS | 06122011
Bottom: MICHAELS | 06122011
